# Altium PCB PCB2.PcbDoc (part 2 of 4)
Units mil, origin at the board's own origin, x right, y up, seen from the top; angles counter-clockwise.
Board outline 7170.03 x 5785.03 mil, 4 copper layers (Top Layer, GND, PWR, Bottom Layer), stack 22.378 mil thick; 348 components, 320 nets, 1937 pads, 429 vias.
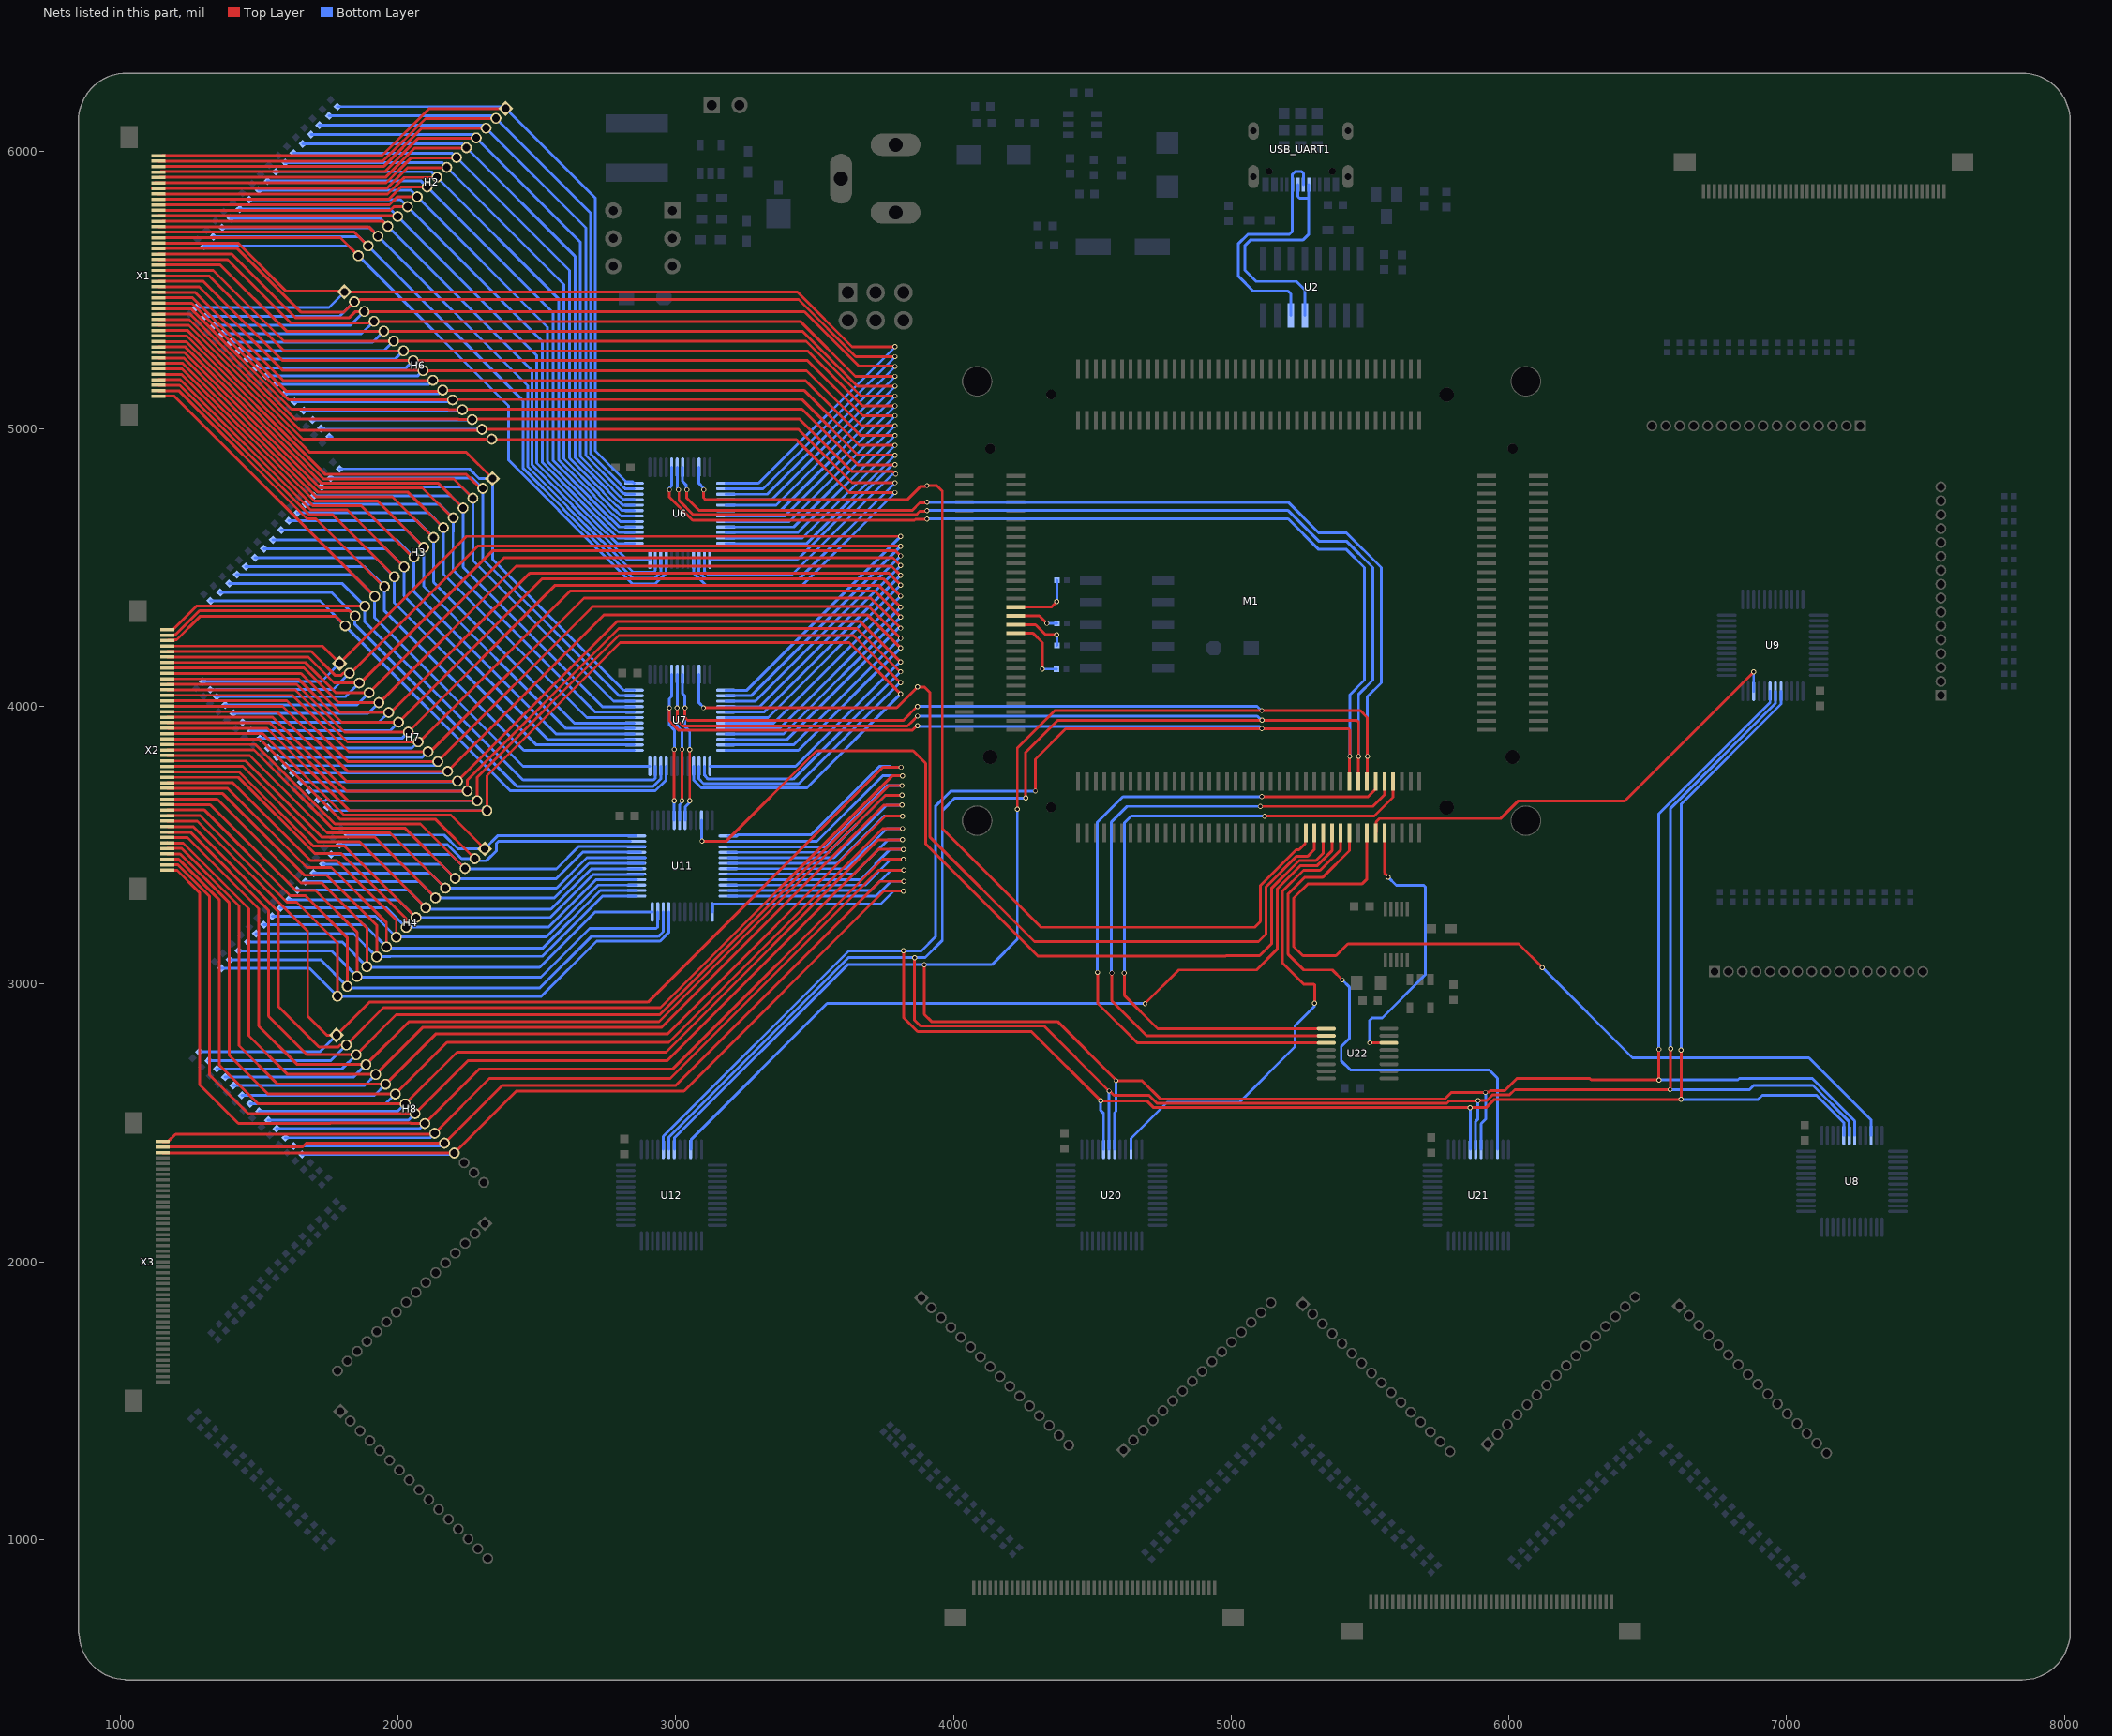
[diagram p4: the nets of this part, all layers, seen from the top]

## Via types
v1: diameter 18, hole 12, Top Layer to Bottom Layer, 429 vias

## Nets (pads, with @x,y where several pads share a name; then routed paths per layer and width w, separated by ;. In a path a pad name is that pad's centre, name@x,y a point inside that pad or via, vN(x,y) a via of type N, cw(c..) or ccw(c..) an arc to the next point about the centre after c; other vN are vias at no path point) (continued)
A2: M1.J4_63 U6.17 U7.17 U8.17 U9.17 U11.17 U12.17 U20.17 U21.17 | length 15635
  Top Layer w10: v1(2977.16,3994.49) 2977.16,3947.84 3011.53,3913.47 3851.3,3913.47 3867.84,3930 v1(3870,3930) ; v1(2977.16,4780) 2977.16,4753.53 3060.69,4670 3858.95,4670 3862.95,4674 3904,4674 v1(3905,4675) ; v1(2994.37,3660) v1(2994.37,3845) ; v1(3820,3119.81) 3820,2880 3870.63,2829.37 4280.63,2829.37 v1(4530,2580) 4695.68,2580 4720.68,2555 v1(5860,2555) 5917.53,2555 5947.53,2585 v1(6620,2585) v1(6620,2762.16) ; v1(4295,3695) 4295,3810 4405,3920 v1(5110,3920) 5421.15,3920 5427.01,3914.14 v1(5427.01,3820) 5426.24,3819.23 5426.24,3730.06 M1.J4_63@5425.47,3729.29 M1.J4_63@5425,3728.82
  Bottom Layer w10: U12.17@2955.47,2405.36 2955.47,2451.67 3623.61,3119.81 v1(3820,3119.81) 3884.81,3119.81 3935,3170 3935,3640 3990,3695 v1(4295,3695) ; v1(2977.16,4780) 2977.16,4785.94 2985.47,4794.25 U6.17@2985.47,4860.36 ; U7.17@2985.47,4115.36 2985.47,4035.47 2977.16,4027.16 v1(2977.16,3994.49) 2977.16,3932.84 2995,3915 2995,3845.63 v1(2994.37,3845) ; U11.17@2994.37,3590.71 v1(2994.37,3660) ; v1(3870,3930) 3871.53,3928.47 5099.37,3928.47 5107.84,3920 v1(5110,3920) ; v1(3905,4675) 5205,4675 5315,4565 5415,4565 5480,4500 5480,4095 5427.01,4042.01 v1(5427.01,3820) ; v1(4530,2580) 4530,2545.06 4540.47,2534.59 U20.17@4540.47,2405.36 ; v1(5860,2555) 5860.47,2554.53 U21.17@5860.47,2405.36 ; v1(6620,2585) 6897.15,2585 6912.15,2600 7107.14,2600 7205.47,2501.67 U8.17@7205.47,2455.36 ; v1(6620,2762.16) 6620,3648.8 6979.53,4008.33 U9.17@6979.53,4054.64
A3: M1.J4_65 U6.18 U7.18 U8.18 U9.18 U11.18 U12.18 U20.18 U21.18 | length 15711.1
  Top Layer w10: v1(3005.16,3995) 3005.16,3949.84 3025.53,3929.47 3834.47,3929.47 3852.52,3947.52 v1(3870,3965) ; v1(3010,4780) 3011.53,4778.47 3011.53,4741.78 3063.31,4690 3866.21,4690 3878.53,4702.32 3902.32,4702.32 v1(3905,4705) ; v1(3022.37,3660) v1(3022.37,3845) ; v1(3860,3095) 3860,2870 3880.94,2849.06 4325.94,2849.06 v1(4560,2615) 4562.16,2615 4577.84,2599.33 4704.2,2599.33 4732.52,2571 5776.27,2571 5785.27,2580 5888.26,2580 v1(5889.13,2580.87) ; v1(4260,3670) 4260,3835 4375,3950 5109.8,3950 v1(5110.31,3950.5) ; v1@5110,3950 5452.65,3950 5458.51,3944.14 v1(5458.51,3820) 5457.74,3819.23 5457.74,3730.06 M1.J4_65@5456.97,3729.29 ; v1@5890,2580 5890.87,2580.87 5920.77,2580.87 5940.9,2601 6001.94,2601 6020.94,2620 v1(6580,2620) 6581.53,2621.53 6581.53,2627.19 6582,2627.66 v1(6582,2767)
  Bottom Layer w10: U12.18@2975.16,2405.36 2975.36,2405.55 2975.36,2448.93 3622.23,3095.81 3859.19,3095.81 v1(3860,3095) 3860.81,3095.81 3898.24,3095.81 3960,3157.57 3960,3625 4005,3670 v1(4260,3670) ; U7.18@3005.16,4115.36 v1(3005.16,3995) 3005.16,3928.92 3023,3911.08 3023,3845.63 v1(3022.37,3845) ; U6.18@3005.16,4860.36 3005.16,4787 3010,4782.16 v1(3010,4780) ; U11.18@3014.06,3590.71 3014.06,3645.75 3022.37,3654.06 v1(3022.37,3660) ; v1(3870,3965) 5093.65,3965 5108.14,3950.5 v1(5110.31,3950.5) ; v1(3905,4705) 5205,4705 5315,4595 5415,4595 5510,4500 5510,4095 5458.51,4043.51 v1(5458.51,3820) ; v1(4560,2615) 4560.08,2614.92 4560.08,2405.44 U20.18@4560.16,2405.36 ; U21.18@5880.16,2405.36 5880.16,2505.75 5888.47,2514.06 5888.47,2580.21 v1(5889.13,2580.87) ; v1(6580,2620) 6865.97,2620 6880.97,2635 7094.77,2635 7225.16,2504.61 U8.18@7225.16,2455.36 ; v1(6582,2767) 6582,3633.42 6959.84,4011.26 U9.18@6959.84,4054.64
A4: M1.J4_67 U6.19 U7.19 U8.19 U9.19 U11.19 U12.19 U20.19 U21.19 | length 15781.3
  Top Layer w10: v1(3033.16,3995) 3033.16,3959.29 3042.45,3950 3820,3950 v1(3870,4000) ; v1(3040,4780) 3040,4749.75 3064.75,4725 3083.75,4706 3852.21,4706 3878.53,4732.32 3902.32,4732.32 v1(3905,4735) ; v1(3050.37,3660) v1(3050.37,3844.63) ; v1(3895,3070) 3895,2890.86 3920.8,2865.06 4374.94,2865.06 4581,2659 4581,2656.16 v1(4585,2652.16) 4679.19,2652.16 4744.36,2587 5769.65,2587 5791.65,2609 5850.98,2609 5851.98,2610 v1(5915,2610) 5916.53,2611.53 5928.8,2611.53 5934.27,2617 5985.74,2617 6028.74,2660 6290.79,2660 6295.79,2655 v1(6540,2655) v1(6540,2765) ; v1(4230,3630) 4230,3850 4365,3985 v1(5110,3985) 5465,3985 5490,3960 v1(5490,3820) 5489.23,3819.23 5489.23,3730.06 M1.J4_67@5488.46,3729.29
  Bottom Layer w10: U12.19@2994.84,2405.36 2994.84,2445.79 3619.05,3070 v1(3895,3070) 4138.43,3070 4230,3161.57 v1(4230,3630) ; U7.19@3024.84,4115.36 3024.84,4045.16 3033.16,4036.84 v1(3033.16,3995) 3033.16,3926.84 3050.37,3909.63 v1(3050.37,3844.63) ; U6.19@3024.84,4860.36 3024.84,4809.92 3038.47,4796.29 3038.47,4781.53 v1(3040,4780) ; U11.19@3033.74,3590.71 3033.74,3637.43 3050.37,3654.06 v1(3050.37,3660) ; v1(3870,4000) 5092.84,4000 5107.84,3985 v1(5110,3985) ; v1(3905,4735) 5205,4735 5315,4625 5415,4625 5540,4500 5540,4085 5490,4035 v1(5490,3820) ; U20.19@4579.84,2405.36 4579.84,2536.9 4585,2542.06 v1(4585,2652.16) ; U21.19@5899.84,2405.36 5899.84,2497.43 5916.47,2514.06 5916.47,2608.53 v1(5915,2610) ; v1(6540,2655) 6824.78,2655 6829.78,2660 7092.4,2660 7244.84,2507.56 U8.19@7244.84,2455.36 ; v1(6540,2765) 6540,3614.05 6940.16,4014.21 U9.19@6940.16,4054.64
A5: M1.J4_69 U22.11 | length 2612.8
  Top Layer w10: v1(4518.03,3041.97) 4519.56,3040.44 4519.56,2930.44 4661.61,2788.39 U22.11@5342.18,2788.39 ; v1(5110,3675) 5492.24,3675 5519.96,3702.72 M1.J4_69@5519.96,3729.29
  Bottom Layer w10: v1(4518.03,3041.97) 4518.03,3583.03 4610,3675 v1(5110,3675)
A6: M1.J4_71 U22.10 | length 2539.4
  Top Layer w10: v1(4570,3040) 4570,2940 4696.02,2813.98 U22.10@5342.18,2813.98 ; v1(5105,3640) 5510,3640 5551.46,3681.46 M1.J4_71@5551.46,3729.29
  Bottom Layer w10: v1(4570,3040) 4569.03,3040.97 4569.03,3584.03 4625,3640 v1(5105,3640)
A7: M1.J4_73 U22.9 | length 2459.8
  Top Layer w10: v1(4615,3040) 4615,2960 4735.43,2839.57 U22.9@5342.18,2839.57 ; v1(5120,3605) 5515,3605 5582.95,3672.95 M1.J4_73@5582.95,3729.29
  Bottom Layer w10: v1(4615,3040) 4615,3580 4640,3605 v1(5120,3605)
CH340_N: U2.6 USB_UART1.5 USB_UART1.7 | length 915.4
  Bottom Layer w10: U2.6@5215,5407.64 5215,5485 5205,5495 5080,5495 5025,5550 5025,5665 5060,5700 5210,5700 5220.47,5710.47 USB_UART1.5@5220.47,5878.05 5220.47,5915.47 5230,5925 5253.98,5925 5259.84,5919.14 USB_UART1.7@5259.84,5878.05
CH340_P: U2.5 USB_UART1.6 USB_UART1.8 | length 934.2
  Bottom Layer w10: USB_UART1.6@5240.16,5878.05 5240.16,5835.86 5246.02,5830 5279.53,5830 ; U2.5@5265,5407.64 5265,5500 5235,5530 5090,5530 5050,5570 5050,5660 5070,5680 5259.05,5680 5279.53,5700.47 5279.53,5830 ; USB_UART1.8@5279.53,5878.05 5279.53,5830
EN0: M1.J4_72 U22.6 | length 1048.1
  Top Layer w10: v1(5498.74,2788.39) U22.6@5567.82,2788.39 ; M1.J4_72@5551.46,3544.25 5551.46,3400.7 5565,3387.16 v1(5565,3385)
  Bottom Layer w10: v1(5498.74,2788.39) 5498.74,2869.66 5507.47,2878.39 5543.39,2878.39 5699,3034 5699,3350.14 5693.14,3356 5594,3356 v1(5565,3385)
EN1: M1.J4_54 U6.22 | length 3915.6
  Top Layer w10: v1(3100.53,4780) 3100.53,4750.86 3106.39,4745 3835,4745 3882.32,4792.32 3902.32,4792.32 v1(3905,4795) 3940,4795 3960,4775 3960,3560 4315.43,3204.57 5084.57,3204.57 5105,3225 5105,3355 5233.78,3483.78 5243.78,3483.78 5266.06,3506.06 5266.06,3542.36 M1.J4_54@5267.95,3544.25
  Bottom Layer w10: U6.22@3083.9,4860.36 3083.9,4802.57 3100.53,4785.94 v1(3100.53,4780)
EN2: M1.J4_56 U7.22 | length 3339
  Top Layer w10: v1(3100,3995) 3796.06,3995 3870,4068.94 v1(3870,4070) 3895,4070 3916,4049 3916,3529 4291.61,3153.39 5098.39,3153.39 5125,3180 5125,3350 5236,3461 5276,3461 5299.45,3484.45 M1.J4_56@5299.45,3544.25
  Bottom Layer w10: U7.22@3083.9,4115.36 3083.9,4012.84 3100,3996.74 v1(3100,3995)
EN3: M1.J4_58 U11.22 | length 3266.9
  Top Layer w10: v1(3095,3515) 3181.98,3515 3506.98,3840 3855,3840 3900,3795 3900,3505 4304,3101 4980.85,3101 4982.05,3102.2 5102.2,3102.2 5145,3145 5145,3345 5245,3445 5305,3445 5330.95,3470.95 M1.J4_58@5330.95,3544.25
  Bottom Layer w10: U11.22@3092.8,3590.71 3092.8,3519.36 3095,3517.16 v1(3095,3515)
EN4: M1.J4_60 U12.22 | length 2965
  Top Layer w10: v1(4690,2930) 4811.02,3051.02 5091.02,3051.02 5165,3125 5165,3342.37 5248.63,3426 5308.63,3426 5362.44,3479.81 M1.J4_60@5362.44,3544.25
  Bottom Layer w10: U12.22@3053.9,2405.36 3053.9,2435.55 3057.07,2438.72 3057.07,2442.12 3544.95,2930 v1(4690,2930)
EN5: M1.J4_62 U20.22 | length 1756.4
  Top Layer w10: v1(5300,2931) 5300,2997.84 5298,2999.84 5288.03,2999.84 5260.9,2999.84 5185,3075.74 5185,3335 5260,3410 5320,3410 5393.98,3483.98 M1.J4_62@5393.98,3544.25
  Bottom Layer w10: U20.22@4638.9,2405.36 4639.1,2405.55 4639.1,2444.6 4769.05,2574.55 5029.55,2574.55 5230,2775 5230,2850 5298.53,2918.53 5298.53,2929.53 v1(5300,2931)
EN6: M1.J4_64 U21.22 | length 1957.9
  Top Layer w10: v1(5400,3015) 5363.98,3051.02 5260.9,3051.02 5205,3106.92 5205,3325 5265,3385 5330,3385 5425.47,3480.47 M1.J4_64@5425.47,3544.25
  Bottom Layer w10: v1(5400,3015) 5425,2990 5425,2804 5396,2775 5396,2724 5428.67,2691.33 5928.67,2691.33 5958.9,2661.1 U21.22@5958.9,2405.36
EN7: M1.J4_68 U8.22 | length 3061.1
  Top Layer w10: M1.J4_68@5488.46,3544.25 5488.46,3378.46 5470,3360 5275,3360 5225,3310 5225,3135 5257.8,3102.2 5377.2,3102.2 5420,3145 6035,3145 v1(6120,3060)
  Bottom Layer w10: v1(6120,3060) 6445,2735 7080,2735 7303.9,2511.1 U8.22@7303.9,2455.36
EN8: M1.J4_70 U9.22 | length 1692.8
  Top Layer w10: M1.J4_70@5519.96,3544.25 5521.71,3546 5521.71,3584.07 5533.82,3596.18 5969.61,3596.18 6032.17,3658.74 6415.94,3658.74 v1(6881.1,4123.9)
  Bottom Layer w10: U9.22@6881.1,4054.64 v1(6881.1,4123.9)
FPGA_TCK: M1.J3_37 R1.1 | length 255.5
  Top Layer w10: M1.J3_37@4224.54,4262.84 4287.16,4262.84 4320,4230 v1(4320,4135)
  Bottom Layer w10: v1(4320,4135) 4320.5,4134.5 4370.5,4134.5 R1.1@4371,4134
FPGA_TDI: M1.J3_31 R4.1 | length 232.6
  Top Layer w10: M1.J3_31@4224.54,4357.32 4352.32,4357.32 v1(4372,4377)
  Bottom Layer w10: v1(4372,4377) R4.1@4372,4454
FPGA_TDO: M1.J3_35 R2.1 | length 201.5
  Top Layer w10: M1.J3_35@4224.54,4294.33 4295.67,4294.33 4332,4258 v1(4372,4258)
  Bottom Layer w10: R2.1@4372,4219 v1(4372,4258)
FPGA_TMS: M1.J3_33 R3.1 | length 158.6
  Top Layer w10: M1.J3_33@4224.54,4325.83 4309.17,4325.83 v1(4336,4299)
  Bottom Layer w10: v1(4336,4299) R3.1@4372,4299
G0: H2.1 R14.2 U6.12 X1.1 | length 3469.6
  Top Layer w10: X1.1@1151.42,5983.07 1942.75,5983.07 2111.85,6152.17 2366.4,6152.17 2367.07,6152.84 H2.1@2387.84,6152.84
  Bottom Layer w10: R14.2@1781.96,6159.43 2381.26,6159.43 H2.1@2387.84,6152.84 2710,5830.69 2710,4920 2821.73,4808.27 2844.64,4808.27 U6.12@2849.64,4803.27
G1: H2.2 R16.2 U6.11 X1.2 | length 3442.2
  Top Layer w10: X1.2@1137.7,5963.39 1945.69,5963.39 2099.12,6116.82 2351.82,6116.82 H2.2@2352.49,6117.49
  Bottom Layer w10: R16.2@1751.96,6125.94 2344.04,6125.94 H2.2@2352.49,6117.49 2694,5775.97 2694,4908.15 2803.21,4798.94 2803.21,4796.43 2812.88,4786.76 2816.27,4786.76 2819.45,4783.58 U6.11@2849.64,4783.58
G2: H2.3 R18.2 U6.10 X1.3 | length 3389.2
  Top Layer w10: X1.3@1149.42,5945 1949.93,5945 2086.39,6081.46 2316.46,6081.46 H2.3@2317.13,6082.13
  Bottom Layer w10: R18.2@1716.96,6092.44 2306.82,6092.44 H2.3@2317.13,6082.13 2676.4,5722.87 2676.4,4902.76 2787.21,4791.95 2787.21,4789.8 2806.26,4770.76 2808.4,4770.76 2812.09,4767.07 2816.28,4767.07 2819.45,4763.9 U6.10@2849.64,4763.9
G3: H2.4 R20.2 U6.9 X1.4 | length 3347.4
  Top Layer w10: X1.4@1145.59,5925 1952.56,5925 2073.66,6046.11 2281.11,6046.11 H2.4@2281.78,6046.78
  Bottom Layer w10: R20.2@1686.96,6058.95 2269.61,6058.95 H2.4@2281.78,6046.78 2656.71,5671.84 2656.71,4899.82 2771.21,4785.32 2771.21,4783.18 2799.63,4754.76 2801.77,4754.76 2812.12,4744.41 2849.45,4744.41 U6.9@2849.64,4744.21
G4: H2.5 R22.2 U6.8 X1.5 | length 3304.5
  Top Layer w10: X1.5@1142.83,5905 1955.18,5905 2060.93,6010.75 2245.75,6010.75 H2.5@2246.42,6011.42
  Bottom Layer w10: R22.2@1656.96,6025.45 2232.39,6025.45 H2.5@2246.42,6011.42 2637.03,5620.82 2637.03,4896.87 2755.21,4778.69 2755.21,4776.55 2793,4738.76 2795.14,4738.76 2809.18,4724.73 2849.45,4724.73 U6.8@2849.64,4724.53
G5: H2.6 R24.2 U6.7 X1.6 | length 3280.2
  Top Layer w10: X1.6@1124.56,5885 1957.81,5885 2048.21,5975.4 2210.4,5975.4 H2.6@2211.07,5976.07
  Bottom Layer w10: R24.2@1624.01,5991.96 2195.17,5991.96 H2.6@2211.07,5976.07 2617.34,5569.8 2617.34,4893.94 2739.21,4772.06 2739.21,4769.92 2786.37,4722.76 2788.52,4722.76 2806.24,4705.04 2849.45,4705.04 U6.7@2849.64,4704.84
G6: H2.7 R26.2 U6.6 X1.7 | length 3244.1
  Top Layer w10: X1.7@1115.01,5865 1960.44,5865 2035.48,5940.04 2175.04,5940.04 H2.7@2175.71,5940.71
  Bottom Layer w10: R26.2@1594.01,5958.46 2157.96,5958.46 H2.7@2175.71,5940.71 2597.66,5518.76 2597.66,4890.99 2723.21,4765.44 2723.21,4763.29 2779.75,4706.76 2781.89,4706.76 2803.49,4685.16 U6.6@2849.64,4685.16
G7: H2.8 R28.2 U6.5 X1.8 | length 3182.1
  Top Layer w10: X1.8@1135.49,5845 1963.07,5845 2022.75,5904.68 2139.68,5904.68 H2.8@2140.36,5905.36
  Bottom Layer w10: R28.2@1559.91,5924.97 2120.74,5924.97 H2.8@2140.36,5905.36 2577.97,5467.74 2577.97,4888.05 2707.21,4758.81 2707.21,4756.67 2773.12,4690.76 2775.26,4690.76 2800.55,4665.47 U6.5@2849.64,4665.47
G8: H2.9 R30.2 U6.4 X1.9 | length 3138.7
  Top Layer w10: X1.9@1133.06,5825.6 1966.29,5825.6 2010.02,5869.33 2104.33,5869.33 H2.9@2105,5870
  Bottom Layer w10: R30.2@1529.91,5891.47 2083.53,5891.47 H2.9@2105,5870 2558.29,5416.71 2558.29,4885.1 2691.21,4752.18 2691.21,4750.04 2766.49,4674.76 2768.63,4674.76 2797.6,4645.79 U6.4@2849.64,4645.79
G9: H2.10 R32.2 U6.3 X1.10 | length 3089.2
  Top Layer w10: X1.10@1137.76,5805.91 1969.23,5805.91 1997.3,5833.97 2068.97,5833.97 H2.10@2069.64,5834.64
  Bottom Layer w10: R32.2@1499.01,5857.98 2046.31,5857.98 H2.10@2069.64,5834.64 2538.6,5365.69 2538.6,4882.17 2675.21,4745.55 2675.21,4743.41 2759.86,4658.76 2762.01,4658.76 2794.66,4626.1 U6.3@2849.64,4626.1
G10: H2.11 R34.2 U6.2 X1.11 | length 3051.9
  Top Layer w10: X1.11@1134.66,5785.32 1971.26,5785.32 1984.57,5798.62 2033.62,5798.62 H2.11@2034.29,5799.29
  Bottom Layer w10: R34.2@1464.01,5824.49 2009.09,5824.49 H2.11@2034.29,5799.29 2518.92,5314.66 2518.92,4879.22 2659.21,4738.93 2659.21,4736.78 2753.24,4642.76 2755.38,4642.76 2791.72,4606.42 U6.2@2849.64,4606.42
G11: H2.12 R36.2 U6.1 X1.12 | length 3008.8
  Top Layer w10: X1.12@1137.76,5766.54 1996.33,5766.54 H2.12@1998.93,5763.93
  Bottom Layer w10: R36.2@1430.09,5790.99 1971.88,5790.99 H2.12@1998.93,5763.93 2499.23,5263.64 2499.23,4876.28 2643.21,4732.3 2643.21,4730.16 2746.61,4626.76 2748.75,4626.76 2788.78,4586.73 U6.1@2849.64,4586.73
G12: H2.13 R38.2 U6.48 X1.13 | length 3040.1
  Top Layer w10: X1.13@1151.42,5746.85 1945.31,5746.85 H2.13@1963.58,5728.58
  Bottom Layer w10: R38.2@1397.14,5757.5 1934.66,5757.5 H2.13@1963.58,5728.58 2483.23,5208.93 2483.23,4869.66 2627.21,4725.67 2627.21,4723.53 2739.98,4610.76 2742.12,4610.76 2824.96,4527.92 2906.26,4527.92 2906.73,4528.4 U6.48@2906.73,4529.64
G13: H2.14 R40.2 U6.47 X1.14 | length 3092.6
  Top Layer w10: X1.14@1137.76,5727.17 1894.28,5727.17 H2.14@1928.22,5693.22
  Bottom Layer w10: R40.2@1367.14,5724 1897.44,5724 H2.14@1928.22,5693.22 2467.23,5154.22 2467.23,4863.03 2611.21,4719.04 2611.21,4716.9 2733.35,4594.76 2735.5,4594.76 2847.04,4483.21 2920.56,4483.21 2926.42,4489.07 U6.47@2926.42,4529.64
G14: H2.15 R42.2 U6.46 X1.15 | length 3097
  Top Layer w10: X1.15@1136.07,5708.39 1842.35,5708.39 H2.15@1892.87,5657.87
  Bottom Layer w10: R42.2@1335.09,5690.51 1860.23,5690.51 H2.15@1892.87,5657.87 2451.23,5099.51 2451.23,4856.4 2595.21,4712.42 2595.21,4710.27 2726.73,4578.76 2728.87,4578.76 2846.27,4461.35 2924.13,4461.35 2946.1,4483.33 U6.46@2946.1,4529.64
G15: H2.16 R44.2 U6.45 X1.16 | length 3092.9
  Top Layer w10: X1.16@1137.76,5687.8 1792.23,5687.8 H2.16@1857.51,5622.51
  Bottom Layer w10: R44.2@1302.14,5657.01 1823.01,5657.01 H2.16@1857.51,5622.51 2398.24,5081.79 2398.24,4886.76 2579.21,4705.79 ; 2579.21,4703.65 2720.1,4562.76 2722.24,4562.76 2843.79,4441.21 2926.61,4441.21 2965.79,4480.39 U6.45@2965.79,4529.64
G16: H6.1 R46.2 U6.25 X1.17 | length 4182.8
  Top Layer w10: X1.17@1137.76,5668.11 1424.52,5668.11 1597.63,5495 1784.23,5495 1786.74,5492.49 1789.26,5495 1807.51,5495 H6.1@1810.03,5492.49 ; H6.1@1807.51,5492.49 1828.28,5492.49 1828.95,5491.82 3438.18,5491.82 3635.04,5294.96 v1(3790,5294.96)
  Bottom Layer w10: R46.2@1272.59,5436.51 1751.54,5436.51 H6.1@1807.51,5492.49 ; U6.25@3180.36,4803.27 3298.31,4803.27 v1(3790,5294.96)
G17: H6.2 R48.2 U6.26 X1.18 | length 4209.9
  Top Layer w10: X1.18@1137.76,5648.43 1421.57,5648.43 1650,5420 1805.74,5420 H6.2@1837.3,5451.56 ; H6.2@1842.87,5457.13 1848.49,5462.75 1861.16,5462.75 1863.41,5465 3442.37,5465 3647.91,5259.46 v1(3790,5259.46)
  Bottom Layer w10: R48.2@1304.64,5403.56 1789.3,5403.56 H6.2@1842.87,5457.13 ; U6.26@3180.36,4783.58 3314.12,4783.58 v1(3790,5259.46)
G18: H6.3 R50.2 U6.27 X1.19 | length 4192.7
  Top Layer w10: X1.19@1137.76,5628.74 1401.26,5628.74 1630,5400 1825,5400 1846.78,5421.78 H6.3@1878.22,5421.78 ; H6.3@1889.05,5410.95 1899.21,5421.11 3463.64,5421.11 3659.25,5225.5 3788.47,5225.5 v1(3790,5223.97)
  Bottom Layer w10: R50.2@1337.59,5371.51 1827.96,5371.51 H6.3@1878.22,5421.78 ; U6.27@3180.36,4763.9 3329.93,4763.9 v1(3790,5223.97)
G19: H6.4 R52.2 U6.28 X1.20 | length 4190
  Top Layer w10: X1.20@1137.76,5609.06 1385.94,5609.06 1615,5380 1907.16,5380 H6.4@1913.58,5386.42 3448.58,5386.42 3646.53,5188.47 v1(3790,5188.47)
  Bottom Layer w10: R52.2@1367.59,5341.51 1868.67,5341.51 H6.4@1913.58,5386.42 ; U6.28@3180.36,4744.21 3345.74,4744.21 v1(3790,5188.47)
G20: H6.5 R54.2 U6.29 X1.21 | length 4187.8
  Top Layer w10: X1.21@1137.76,5589.37 1360.63,5589.37 1598.93,5351.07 H6.5@1948.93,5351.07 3456.56,5351.07 3654.65,5152.97 v1(3790,5152.97)
  Bottom Layer w10: R54.2@1397.59,5311.51 1909.38,5311.51 H6.5@1948.93,5351.07 ; U6.29@3180.36,4724.53 3361.56,4724.53 v1(3790,5152.97)
G21: H6.6 R56.2 U6.30 X1.22 | length 4191
  Top Layer w10: X1.22@1137.76,5569.69 1335.31,5569.69 1590,5315 1984.29,5315 1984.33,5315.04 3469.96,5315.04 3667.52,5117.48 v1(3790,5117.48)
  Bottom Layer w10: R56.2@1427.59,5281.51 1950.09,5281.51 H6.6@1984.29,5315.71 ; U6.30@3180.36,4704.84 3377.36,4704.84 v1(3790,5117.48)
G22: H6.7 R58.2 U6.31 X1.23 | length 4194.1
  Top Layer w10: X1.23@1137.76,5550 1320,5550 1590,5280 3475,5280 3673.02,5081.98 v1(3790,5081.98)
  Bottom Layer w10: R58.2@1457.59,5251.51 1990.8,5251.51 H6.7@2019.64,5280.36 ; U6.31@3180.36,4685.16 3393.18,4685.16 v1(3790,5081.98)
G23: H6.8 R60.2 U6.32 X1.24 | length 4195.2
  Top Layer w10: X1.24@1137.76,5530.32 1299.68,5530.32 1585,5245 H6.8@2055,5245 3475,5245 3673.51,5046.49 v1(3790,5046.49)
  Bottom Layer w10: R60.2@1490.54,5219.47 2029.46,5219.47 H6.8@2055,5245 ; U6.32@3180.36,4665.47 3408.98,4665.47 v1(3790,5046.49)
G24: H6.9 R62.2 U6.33 X1.25 | length 4186.4
  Top Layer w10: X1.25@1137.76,5510.63 1284.37,5510.63 1585.36,5209.64 H6.9@2090.36,5209.64 ; H6.9@2101.19,5198.81 2111.34,5208.97 3471.03,5208.97 3669.01,5010.99 v1(3790,5010.99)
  Bottom Layer w10: R62.2@1525.54,5189.47 2070.18,5189.47 H6.9@2090.36,5209.64 ; U6.33@3180.36,4645.79 3424.8,4645.79 v1(3790,5010.99)
G25: H6.10 R64.2 U6.34 X1.26 | length 4191.4
  Top Layer w10: X1.26@1137.76,5490.95 1269.05,5490.95 1586.38,5173.62 3466.38,5173.62 3664.5,4975.5 v1(3790,4975.5)
  Bottom Layer w10: R64.2@1560.54,5159.47 2110.89,5159.47 H6.10@2125.71,5174.29 ; U6.34@3180.36,4626.1 3440.6,4626.1 v1(3790,4975.5)
G26: H6.11 R66.2 U6.35 X1.27 | length 4196.4
  Top Layer w10: X1.27@1137.76,5471.26 1261.03,5471.26 1597.29,5135 2161.07,5135 2164.33,5138.26 3461.74,5138.26 3660,4940 v1(3790,4940)
  Bottom Layer w10: R66.2@1592.59,5126.51 2148.65,5126.51 H6.11@2161.07,5138.93 ; U6.35@3180.36,4606.42 3456.42,4606.42 v1(3790,4940)
G27: H6.12 R68.2 U6.36 X1.28 | length 4193.2
  Top Layer w10: X1.28@1137.76,5451.58 1258.08,5451.58 1606.09,5103.58 H6.12@2196.42,5103.58 ; H6.12@2195.87,5104.25 2196.42,5104.8 3455.2,5104.8 3655.5,4904.5 v1(3790,4904.5)
  Bottom Layer w10: R68.2@1627.59,5096.51 2189.36,5096.51 H6.12@2196.42,5103.58 ; U6.36@3180.36,4586.73 3472.23,4586.73 v1(3790,4904.5)
G28: H6.13 R70.2 U6.37 X1.29 | length 4266.4
  Top Layer w10: X1.29@1137.76,5431.89 1255.15,5431.89 1617.04,5070 2180.95,5070 2182.05,5068.89 2230.67,5068.89 2231.78,5070 3455,5070 3655,4870 v1(3790,4870)
  Bottom Layer w10: R70.2@1660.54,5064.47 2228.02,5064.47 H6.13@2231.78,5068.22 ; U6.37@3123.27,4529.64 3123.39,4529.64 3123.74,4530 3440,4530 3778.47,4868.47 3788.47,4868.47 v1(3790,4870)
G29: H6.14 R72.2 U6.38 X1.30 | length 4353.5
  Top Layer w10: X1.30@1137.76,5412.21 1252.2,5412.21 1630.41,5034 2216.95,5034 2217.41,5033.54 2266.67,5033.54 2267.13,5034 3446,5034 3634,4846 3780.78,4846 3789.81,4836.97 v1(3791.97,4836.97)
  Bottom Layer w10: R72.2@1692.59,5031.51 2265.78,5031.51 H6.14@2267.13,5032.87 ; U6.38@3103.58,4529.64 3103.58,4486.27 3113.85,4476 3421,4476 3780.44,4835.44 3790.44,4835.44 v1(3791.97,4836.97)
G30: H6.15 R74.2 U6.39 X1.31 | length 4384
  Top Layer w10: X1.31@1137.76,5392.52 1249.26,5392.52 1646.78,4995 2302.49,4995 2304.33,4996.84 3443.16,4996.84 3635,4805 v1(3790,4805)
  Bottom Layer w10: R74.2@1722.59,5001.51 1729.67,5001.51 1733.67,4997.51 1748,4997.51 1748.39,4997.9 2302.1,4997.9 H6.15@2302.49,4997.51 ; U6.39@3083.9,4529.64 3083.9,4483.33 3107.23,4460 3445,4460 v1(3790,4805)
G31: H6.16 R76.2 U6.40 X1.32 | length 4422.5
  Top Layer w10: X1.32@1137.76,5372.84 1138.66,5371.94 1247.22,5371.94 1657,4962.16 2335.69,4962.16 2337.84,4960 3435,4960 3625,4770 v1(3790,4770)
  Bottom Layer w10: R76.2@1752.59,4971.51 1759.67,4971.51 1769.02,4962.16 H6.16@2337.84,4962.16 ; U6.40@3064.21,4529.64 3064.21,4480.39 3108.2,4436.4 3456.4,4436.4 v1(3790,4770)
G32: H3.1 R78.2 U7.12 X1.33 | length 2983.2
  Top Layer w10: X1.33@1137.76,5353.15 1243.38,5353.15 1681.53,4915 2245.71,4915 H3.1@2340.36,4820.36
  Bottom Layer w10: R78.2@1790,4855 2257.63,4855 2292.27,4820.36 H3.1@2340.36,4820.36 2340.36,4529.64 2811.53,4058.47 2849.45,4058.47 U7.12@2849.64,4058.27
G33: H3.2 R80.2 U7.11 X1.34 | length 2971.3
  Top Layer w10: X1.34@1137.76,5333.47 1240.43,5333.47 1738.9,4835 2246.67,4835 H3.2@2310.57,4771.1
  Bottom Layer w10: R80.2@1757.95,4822.05 2267.95,4822.05 H3.2@2305,4785 2305,4530 2796.42,4038.58 U7.11@2849.64,4038.58
G34: H3.3 R82.2 U7.10 X1.35 | length 2941
  Top Layer w10: X1.35@1137.76,5313.78 1237.49,5313.78 1732.27,4819 2200.29,4819 H3.3@2269.64,4749.64
  Bottom Layer w10: R82.2@1725,4790 2229.29,4790 H3.3@2269.64,4749.64 2269.65,4525.35 2776.1,4018.9 U7.10@2849.64,4018.9
G35: H3.4 R84.2 U7.9 X1.36 | length 2928.7
  Top Layer w10: X1.36@1137.76,5294.1 1234.55,5294.1 1725.65,4803 2145.58,4803 H3.4@2234.29,4714.29
  Bottom Layer w10: R84.2@1697.05,4757.95 2190.63,4757.95 2224.24,4724.34 H3.4@2234.29,4714.29 2234.29,4500.71 2735.79,3999.21 U7.9@2849.64,3999.21
G36: H3.5 R86.2 U7.8 X1.37 | length 2918
  Top Layer w10: X1.37@1137.76,5274.41 1231.61,5274.41 1719.02,4787 2088,4787 H3.5@2202.99,4672.01
  Bottom Layer w10: R86.2@1667.05,4727.95 2149.92,4727.95 H3.5@2198.93,4678.93 2198.93,4627.3 2198.23,4626.6 2198.23,4491.77 2710.47,3979.53 U7.8@2849.64,3979.53
G37: H3.6 R88.2 U7.7 X1.38 | length 2908.6
  Top Layer w10: X1.38@1137.76,5254.73 1228.66,5254.73 1712.39,4771 2036.16,4771 H3.6@2173.93,4633.23
  Bottom Layer w10: R88.2@1637.95,4697.05 2110.11,4697.05 H3.6@2163.58,4643.58 2163.58,4476.42 2680.16,3959.84 U7.7@2849.64,3959.84
G38: H3.7 R90.2 U7.6 X1.39 | length 2891.8
  Top Layer w10: X1.39@1137.76,5235.04 1225.72,5235.04 1705.76,4755 1980,4755 H3.7@2129.96,4605.04
  Bottom Layer w10: R90.2@1607.05,4667.95 2068.5,4667.95 2120.45,4616 H3.7@2128.22,4608.22 2128.22,4446.78 2634.84,3940.16 U7.6@2849.64,3940.16
G39: H3.8 R92.2 U7.5 X1.40 | length 2884.7
  Top Layer w10: X1.40@1137.76,5215.36 1222.78,5215.36 1699.14,4739 1926.74,4739 H3.8@2103.76,4561.98
  Bottom Layer w10: R92.2@1580,4635 2030.74,4635 H3.8@2092.87,4572.87 2092.87,4432.13 2604.53,3920.47 U7.5@2849.64,3920.47
G40: H3.9 R94.2 U7.4 X1.41 | length 2844.9
  Top Layer w10: X1.41@1137.76,5195.67 1219.84,5195.67 1692.51,4723 1867,4723 H3.9@2049.01,4540.99
  Bottom Layer w10: R94.2@1550,4600 1995.03,4600 H3.9@2057.51,4537.51 2057.51,4412.49 2569.21,3900.79 U7.4@2849.64,3900.79
G41: H3.10 R96.2 U7.3 X1.42 | length 2852
  Top Layer w10: X1.42@1137.76,5175.99 1216.89,5175.99 1685.88,4707 1817.32,4707 H3.10@2029.44,4494.88
  Bottom Layer w10: R96.2@1517.05,4567.95 1956.37,4567.95 2014.54,4509.78 H3.10@2022.16,4502.16 2022.16,4397.84 2538.9,3881.1 U7.3@2849.64,3881.1
G42: H3.11 R98.2 U7.2 X1.43 | length 2830
  Top Layer w10: X1.43@1137.76,5156.3 1213.95,5156.3 1679.25,4691 1764,4691 H3.11@1985,4470
  Bottom Layer w10: R98.2@1485,4535 1918.61,4535 H3.11@1986.8,4466.8 1986.8,4373.2 2498.58,3861.42 U7.2@2849.64,3861.42
G43: H3.12 R100.2 U7.1 X1.44 | length 2822.1
  Top Layer w10: X1.44@1137.76,5136.62 1211.01,5136.62 1672.63,4675 1705,4675 H3.12@1945.88,4434.12
  Bottom Layer w10: R100.2@1452.05,4502.95 1879.94,4502.95 H3.12@1951.45,4431.45 1951.45,4343.55 2453.27,3841.73 U7.1@2849.64,3841.73
G44: H3.13 R102.2 U7.48 X1.45 | length 2894.8
  Top Layer w10: X1.45@1137.76,5116.93 1195.25,5116.93 H3.13@1916.09,4396.09
  Bottom Layer w10: R102.2@1420,4475 1837.18,4475 H3.13@1916.09,4396.09 1916.09,4318.91 2450.36,3784.64 U7.48@2906.73,3784.64
G45: H3.14 R104.2 U7.47 X2.1 | length 2652.4
  Top Layer w10: X2.1@1170,4276.18 1189.68,4276.18 1274.24,4360.74 H3.14@1880.74,4360.74
  Bottom Layer w10: R104.2@1392.05,4442.95 1798.52,4442.95 H3.14@1880.74,4360.74 1880.74,4304.26 2450,3735 2920.15,3735 2926.42,3741.27 U7.47@2926.42,3784.64
G46: H3.15 R106.2 U7.46 X2.2 | length 2670.3
  Top Layer w10: X2.2@1169.94,4256.5 1170.85,4257.41 1194.52,4257.41 1196.39,4259.27 1200.15,4259.27 1285.61,4344.74 1824.84,4344.74 1844.19,4325.38 H3.15@1845.38,4325.38
  Bottom Layer w10: R106.2@1360,4410 1760.76,4410 H3.15@1845.38,4325.38 1845.38,4294.62 2427.79,3712.21 2919.98,3712.21 2946.1,3738.33 U7.46@2946.1,3784.64
G47: H3.16 R108.2 U7.45 X2.3 | length 2680.6
  Top Layer w10: X2.3@1170,4236.81 1170.91,4237.72 1194.57,4237.72 1196.45,4239.59 1203.09,4239.59 1288.5,4325 1775.05,4325 H3.16@1810.03,4290.03
  Bottom Layer w10: R108.2@1325,4380 1720.05,4380 H3.16@1810.03,4290.03 ; H3.16@1810.03,4290.03 2403.79,3696.21 2926.61,3696.21 2965.79,3735.39 U7.45@2965.79,3784.64
G48: H7.1 R110.2 U7.25 X2.4 | length 4233.2
  Top Layer w10: X2.4@1170,4217.13 1727.87,4217.13 H7.1@1789.84,4155.16 2246.64,4611.97 v1(3810,4611.97)
  Bottom Layer w10: R110.2@1297.58,4089.82 1724.49,4089.82 H7.1@1789.84,4155.16 ; U7.25@3180.36,4058.27 3256.3,4058.27 v1(3810,4611.97)
G49: H7.2 R112.2 U7.26 X2.5 | length 4240.7
  Top Layer w10: X2.5@1170,4197.44 1687.56,4197.44 1772.67,4112.33 1796.05,4112.33 1803.53,4119.81 H7.2@1825.19,4119.81 ; H7.2@1830.23,4120.23 2286.97,4576.97 v1(3810,4576.97)
  Bottom Layer w10: R112.2@1324.31,4060.21 1342.38,4060.21 1343.38,4061.21 1766.59,4061.21 H7.2@1825.19,4119.81 ; U7.26@3180.36,4038.58 3271.61,4038.58 v1(3810,4576.97)
G50: H7.3 R114.2 U7.27 X2.6 | length 4261.8
  Top Layer w10: X2.6@1170,4177.76 1677.24,4177.76 1770.55,4084.45 H7.3@1860.55,4084.45 ; H7.3@1862.5,4082.5 2340,4560 3791.97,4560 v1(3810,4541.97)
  Bottom Layer w10: R114.2@1347.58,4034.82 1810.91,4034.82 H7.3@1860.55,4084.45 ; U7.27@3180.36,4018.9 3286.93,4018.9 v1(3810,4541.97)
G51: H7.4 R116.2 U7.28 X2.7 | length 4274.6
  Top Layer w10: X2.7@1170,4158.07 1666.93,4158.07 1775.9,4049.1 H7.4@1895.9,4049.1 2381.8,4535 3781.97,4535 v1(3810,4506.97)
  Bottom Layer w10: R116.2@1377.58,4004.82 1851.63,4004.82 H7.4@1895.9,4049.1 ; U7.28@3180.36,3999.21 3302.24,3999.21 v1(3810,4506.97)
G52: H7.5 R118.2 U7.29 X2.8 | length 4278.4
  Top Layer w10: X2.8@1170,4138.39 1661.61,4138.39 1786.26,4013.74 H7.5@1931.26,4013.74 ; H7.5@1934.65,4014.65 2425,4505 3776.97,4505 v1(3810,4471.97)
  Bottom Layer w10: R118.2@1407.58,3974.82 1892.33,3974.82 H7.5@1931.26,4013.74 ; U7.29@3180.36,3979.53 3317.56,3979.53 v1(3810,4471.97)
G53: H7.6 R120.2 U7.30 X2.9 | length 4291.8
  Top Layer w10: X2.9@1170,4118.7 1651.3,4118.7 1791.61,3978.39 H7.6@1966.61,3978.39 ; H7.6@1970,3975 2475,4480 3766.97,4480 v1(3810,4436.97)
  Bottom Layer w10: R120.2@1440.53,3942.77 1931,3942.77 H7.6@1966.61,3978.39 ; U7.30@3180.36,3959.84 3332.87,3959.84 v1(3810,4436.97) v1@3808.03,4436.97
G54: H7.7 R122.2 U7.31 X2.10 | length 4298.8
  Top Layer w10: X2.10@1170,4099.02 1640.98,4099.02 1796.97,3943.03 H7.7@2001.97,3943.03 ; H7.7@2008.57,3948.57 2520,4460 3746.97,4460 v1(3810,4396.97)
  Bottom Layer w10: R122.2@1470.53,3912.77 1971.71,3912.77 H7.7@2001.97,3943.03 ; U7.31@3180.36,3940.16 3353.19,3940.16 v1(3810,4396.97)
G55: H7.8 R124.2 U7.32 X2.11 | length 4317.7
  Top Layer w10: X2.11@1170,4079.33 1635.67,4079.33 1807.32,3907.68 H7.8@2037.32,3907.68 2566.05,4436.4 3730.57,4436.4 v1(3810,4356.97)
  Bottom Layer w10: R124.2@1502.58,3884.82 2014.47,3884.82 H7.8@2037.32,3907.68 ; U7.32@3180.36,3920.47 3373.5,3920.47 v1(3810,4356.97)
G56: H7.9 R126.2 U7.33 X2.12 | length 4333.1
  Top Layer w10: X2.12@1170,4059.65 1630.35,4059.65 1817.68,3872.32 H7.9@2072.68,3872.32 ; H7.9@2075,3870 2620,4415 3716.97,4415 v1(3810,4321.97)
  Bottom Layer w10: R126.2@1532.58,3849.82 2050.18,3849.82 H7.9@2072.68,3872.32 ; U7.33@3180.36,3900.79 3388.82,3900.79 v1(3810,4321.97)
G57: H7.10 R128.2 U7.34 X2.13 | length 4322.5
  Top Layer w10: X2.13@1170,4039.96 1620.04,4039.96 1823.03,3836.97 H7.10@2108.03,3836.97 ; H7.10@2124.11,3844.11 2670,4390 3701.97,4390 v1(3810,4281.97)
  Bottom Layer w10: R128.2@1564.63,3816.87 2087.94,3816.87 H7.10@2108.03,3836.97 ; U7.34@3180.36,3881.1 3401.1,3881.1 v1@3805,4285
G58: H7.11 R130.2 U7.35 X2.14 | length 4352.9
  Top Layer w10: X2.14@1170,4020.28 1599.72,4020.28 1818.39,3801.61 H7.11@2143.39,3801.61 2701.78,4360 3695,4360 v1(3810,4245)
  Bottom Layer w10: R130.2@1594.63,3786.87 2128.65,3786.87 H7.11@2143.39,3801.61 ; U7.35@3180.36,3861.42 3424.26,3861.42 3807.84,4245 v1(3810,4245)
G59: H7.12 R132.2 U7.36 X2.15 | length 4361.3
  Top Layer w10: X2.15@1170,4000.59 1584.41,4000.59 1818.74,3766.26 H7.12@2178.74,3766.26 2742.49,4330 3690,4330 v1(3810,4210)
  Bottom Layer w10: R132.2@1622.58,3759.82 2172.31,3759.82 H7.12@2178.74,3766.26 ; U7.36@3180.36,3841.73 3441.73,3841.73 v1(3810,4210)
G60: H7.13 R134.2 U7.37 X2.16 | length 4448.5
  Top Layer w10: X2.16@1170,3980.91 1564.09,3980.91 1814.1,3730.9 H7.13@2214.1,3730.9 2788.2,4305 3665,4305 v1(3810,4160)
  Bottom Layer w10: R134.2@1650.53,3727.77 2210.97,3727.77 H7.13@2214.1,3730.9 ; U7.37@3123.27,3784.64 3431.46,3784.64 3806.82,4160 v1(3810,4160)
G61: H7.14 R136.2 U7.38 X2.17 | length 4554.5
  Top Layer w10: X2.17@1170,3961.22 1548.78,3961.22 1814.45,3695.55 2249.39,3695.55 H7.14@2249.45,3695.55 2249.45,3734.45 2795,4280 3651.82,4280 3806.82,4125 v1(3810,4125)
  Bottom Layer w10: R136.2@1680.53,3697.77 1687.61,3697.77 1689.83,3695.55 H7.14@2249.45,3695.55 ; U7.38@3103.58,3784.64 3103.58,3754.45 3106.76,3751.27 3106.76,3747.88 3116.43,3738.21 3423.21,3738.21 v1(3810,4125)
G62: H7.15 R139.2 U7.39 X2.18 | length 4629.9
  Top Layer w10: X2.18@1170,3941.54 1170.91,3940.63 1539.37,3940.63 1819.81,3660.19 H7.15@2284.81,3660.19 2284.81,3744.81 2795,4255 3640,4255 v1(3810,4085)
  Bottom Layer w10: R139.2@1712.58,3664.82 1719.65,3664.82 1724.29,3660.19 1737.36,3660.19 1741.33,3664.16 1750.45,3664.16 1754.42,3660.19 H7.15@2284.81,3660.19 ; U7.39@3083.9,3784.64 3083.9,3738.33 3100.23,3722 3443.21,3722 3806.21,4085 v1(3810,4085)
G63: H7.16 R141.2 U7.40 X2.19 | length 4691.4
  Top Layer w10: X2.19@1170,3921.85 1170.91,3920.94 1529.06,3920.94 1825.16,3624.84 H7.16@2320.16,3624.84 2320.16,3750.16 2800,4230 3625,4230 v1(3810,4045)
  Bottom Layer w10: R141.2@1745.53,3637.77 1752.61,3637.77 1765.54,3624.84 H7.16@2320.16,3624.84 ; U7.40@3064.21,3784.64 3064.21,3735.39 3093.6,3706 3471,3706 v1(3810,4045)
G64: H4.1 R143.2 U11.12 X2.20 | length 2393.2
  Top Layer w10: X2.20@1170,3902.17 1512.83,3902.17 1806.16,3608.84 2190.43,3608.84 H4.1@2312.13,3487.13
  Bottom Layer w10: R143.2@1819.07,3537.01 2166.08,3537.01 2215.96,3487.13 H4.1@2312.13,3487.13 2360,3535 2826.97,3535 2828.15,3533.82 2856.82,3533.82 U11.12@2857.1,3534.1
G65: H4.2 R145.2 U11.11 X2.21 | length 2405.6
  Top Layer w10: X2.21@1170,3882.48 1502.52,3882.48 1792.16,3592.84 2135.72,3592.84 H4.2@2276.78,3451.78
  Bottom Layer w10: R145.2@1789.07,3502.01 2178.46,3502.01 2228.69,3451.78 H4.2@2276.78,3451.78 ; H4.2@2272.89,3436.76 2280.43,3444.29 2318.35,3444.29 2354.97,3480.92 2354.97,3507.34 2362.63,3515 U11.11@2836.93,3515
G66: H4.3 R147.2 U11.10 X2.22 | length 2441.1
  Top Layer w10: X2.22@1170,3862.8 1487.2,3862.8 1773.16,3576.84 2081.01,3576.84 H4.3@2241.42,3416.42
  Bottom Layer w10: R147.2@1759.07,3467.01 2190.83,3467.01 H4.3@2241.42,3416.42 ; H4.3@2241.42,3415 2570,3415 2650,3495 U11.10@2889.77,3495
G67: H4.4 R149.2 U11.9 X2.23 | length 2438
  Top Layer w10: X2.23@1170,3843.11 1481.89,3843.11 1764.16,3560.84 2026.29,3560.84 H4.4@2206.07,3381.07
  Bottom Layer w10: R149.2@1729.07,3432.01 2155.12,3432.01 H4.4@2206.07,3381.07 ; H4.4@2201.1,3380 2570,3380 2665,3475 2827.47,3475 2827.7,3474.76 2873.79,3474.76 U11.9@2874.03,3475
G68: H4.5 R151.2 U11.8 X2.24 | length 2460.8
  Top Layer w10: X2.24@1170,3823.43 1466.57,3823.43 1745.16,3544.84 1971.59,3544.84 H4.5@2170.71,3345.71
  Bottom Layer w10: R151.2@1696.12,3399.96 2116.46,3399.96 H4.5@2170.71,3345.71 2570.83,3345.71 2680.12,3455 U11.8@2890.58,3455
G69: H4.6 R153.2 U11.7 X2.25 | length 2471
  Top Layer w10: X2.25@1170,3803.74 1451.26,3803.74 1726.16,3528.84 1916.87,3528.84 H4.6@2135.36,3310.36
  Bottom Layer w10: R153.2@1667.02,3369.06 2076.65,3369.06 H4.6@2135.36,3310.36 ; H4.6@2128.29,3310 2562.97,3310 2687.97,3435 2827.7,3435 U11.7@2885.18,3435
G70: H4.7 R155.2 U11.6 X2.26 | length 2461
  Top Layer w10: X2.26@1170,3784.06 1440.94,3784.06 1712.16,3512.84 1862.16,3512.84 H4.7@2100,3275
  Bottom Layer w10: R155.2@1637.02,3339.06 2035.94,3339.06 H4.7@2100,3275 ; H4.7@2106.82,3270 2550.8,3270 2695.8,3415 U11.6@2877.39,3415
G71: H4.8 R157.2 U11.5 X2.27 | length 2487.7
  Top Layer w10: X2.27@1170,3764.37 1428.26,3764.37 1695.79,3496.84 1807.45,3496.84 H4.8@2064.64,3239.64
  Bottom Layer w10: R157.2@1607.02,3304.06 2000.23,3304.06 H4.8@2064.29,3240 ; H4.8@2056.72,3240 H4.8@2064.29,3240 ; H4.8@2064.64,3239.64 H4.8@2064.29,3240 ; U11.5@2883.95,3395 2703.64,3395 2548.64,3240 H4.8@2064.29,3240
G72: H4.9 R159.2 U11.4 X2.28 | length 2484.9
  Top Layer w10: X2.28@1170,3744.69 1425.31,3744.69 1700,3470 1795,3470 2029.29,3235.71 H4.9@2029.29,3204.29
  Bottom Layer w10: R159.2@1577.02,3274.06 1959.52,3274.06 H4.9@2028.62,3204.96 ; H4.9@2027.3,3205 2027.34,3204.96 H4.9@2028.62,3204.96 ; H4.9@2029.29,3204.29 H4.9@2028.62,3204.96 ; U11.4@2858.54,3376.15 2712.62,3376.15 2541.48,3205 2079.05,3205 2079.01,3204.96 H4.9@2028.62,3204.96
G73: H4.10 R161.2 U11.3 X2.29 | length 2519
  Top Layer w10: X2.29@1170,3725 1405,3725 1685,3445 1780,3445 1993.93,3231.07 H4.10@1993.93,3168.93
  Bottom Layer w10: R161.2@1547.02,3244.06 1918.81,3244.06 H4.10@1993.26,3169.6 ; H4.10@1985.79,3170 1986.19,3169.6 H4.10@1993.26,3169.6 ; H4.10@1993.93,3168.93 H4.10@1993.26,3169.6 ; U11.3@2858.54,3356.46 2720.78,3356.46 2534.32,3170 2044.05,3170 2043.66,3169.6 H4.10@1993.26,3169.6
G74: H4.11 R163.2 U11.2 X2.30 | length 2537.4
  Top Layer w10: X2.30@1170,3705.32 1386.84,3705.32 1672.71,3419.45 1760.55,3419.45 1958.58,3221.42 H4.11@1958.58,3133.58
  Bottom Layer w10: R163.2@1517.02,3214.06 1878.1,3214.06 H4.11@1958.58,3133.58 ; H4.11@1958.58,3130 2522.15,3130 2728.93,3336.78 U11.2@2858.54,3336.78
G75: H4.12 R165.2 U11.1 X2.31 | length 2571.5
  Top Layer w10: X2.31@1170,3685.63 1369.37,3685.63 1663.07,3391.93 1743.07,3391.93 1923.22,3211.78 H4.12@1923.22,3098.22
  Bottom Layer w10: R165.2@1489.07,3182.01 1839.43,3182.01 H4.12@1921.45,3100 ; H4.12@1909.58,3100 H4.12@1921.45,3100 ; H4.12@1923.22,3098.22 H4.12@1921.45,3100 ; U11.1@2858.27,3317.28 2827.7,3317.28 2737.28,3317.28 2520,3100 1974.05,3100 1972.95,3098.89 1944.21,3098.89 1943.11,3100 H4.12@1921.45,3100
G76: H4.13 R167.2 U11.48 X2.32 | length 2628.7
  Top Layer w10: X2.32@1170,3665.95 1349.05,3665.95 1650.59,3364.41 1725.59,3364.41 1887.87,3202.13 H4.13@1887.87,3062.87
  Bottom Layer w10: R167.2@1459.07,3152.01 1798.72,3152.01 H4.13@1887.87,3062.87 ; H4.13@1885.67,3062.2 1887.87,3060 2510,3060 2710,3260 U11.48@2915.63,3260
G77: H4.14 R169.2 U11.47 X2.33 | length 2692.9
  Top Layer w10: X2.33@1170,3646.26 1323.74,3646.26 1633.11,3336.89 1703.11,3336.89 1852.51,3187.49 H4.14@1852.51,3027.51
  Bottom Layer w10: R169.2@1426.12,3119.96 1760.06,3119.96 H4.14@1852.51,3027.51 ; H4.14@1868.48,3025 2515,3025 2690.32,3200.32 2929.46,3200.32 2935.32,3206.18 U11.47@2935.32,3260
G78: H4.15 R171.2 U11.46 X2.34 | length 2768
  Top Layer w10: X2.34@1170,3626.58 1303.42,3626.58 1611.7,3318.3 1666.7,3318.3 1817.16,3167.84 H4.15@1817.16,2992.16
  Bottom Layer w10: R171.2@1394.07,3087.01 1722.3,3087.01 H4.15@1817.16,2992.16 ; H4.15@1817.16,2986.54 2511.54,2986.54 2696,3171 2937.16,3171 2955,3188.84 U11.46@2955,3260
G79: H4.16 R173.2 U11.45 X2.35 | length 2819.2
  Top Layer w10: X2.35@1170,3606.89 1288.11,3606.89 1600.23,3294.77 1635.23,3294.77 1781.8,3148.2 H4.16@1781.8,2956.8
  Bottom Layer w10: R173.2@1364.07,3057.01 1681.59,3057.01 H4.16@1781.8,2956.8 ; H4.16@1777.65,2955 2515,2955 2715,3155 2943.79,3155 2974.69,3185.9 U11.45@2974.69,3260
G80: H8.1 R175.2 U11.25 X2.36 | length 4785.9
  Top Layer w10: X2.36@1170,3587.21 1277.79,3587.21 1675,3190 1675,2885 1743.58,2816.42 H8.1@1778.58,2816.42 1897.16,2935 2900,2935 3746,3781 v1(3811.69,3781)
  Bottom Layer w10: R175.2@1284.69,2756.89 1719.05,2756.89 H8.1@1778.58,2816.42 ; U11.25@3189.26,3533.63 3219.45,3533.63 3224.45,3538.63 3488.63,3538.63 3735.03,3785.03 3770.26,3785.03 3774.29,3781 v1(3811.69,3781)
G81: H8.2 R177.2 U11.26 X2.37 | length 4823
  Top Layer w10: X2.37@1170,3567.52 1170.91,3566.61 1263.39,3566.61 1569.64,3260.36 1569.64,2919.64 1715.71,2773.58 1784.79,2773.58 1792.27,2781.07 H8.2@1813.93,2781.07 1947.87,2915 2944.75,2915 3779.75,3750 v1(3815.99,3750)
  Bottom Layer w10: R177.2@1317.64,2724.84 1757.71,2724.84 H8.2@1813.93,2781.07 ; U11.26@3189.26,3513.94 3508.94,3513.94 3745,3750 v1(3815.99,3750)
G82: H8.3 R179.2 U11.27 X2.38 | length 4842.1
  Top Layer w10: X2.38@1170,3547.84 1170.91,3546.93 1253.07,3546.93 1534.29,3265.71 1534.29,2884.29 1672.87,2745.71 H8.3@1849.29,2745.71 1993.58,2890 2942.37,2890 3767.37,3715 v1(3815,3715)
  Bottom Layer w10: R179.2@1347.64,2694.84 1798.42,2694.84 H8.3@1849.29,2745.71 ; U11.27@3189.26,3494.26 3539.26,3494.26 3760,3715 v1(3815,3715)
G83: H8.4 R181.2 U11.28 X2.39 | length 4869.4
  Top Layer w10: X2.39@1170,3528.15 1241.85,3528.15 1498.93,3271.07 1498.93,2848.93 1637.51,2710.35 H8.4@1884.65,2710.35 2039.29,2865 2940,2865 3755,3680 v1(3815,3680)
  Bottom Layer w10: R181.2@1377.64,2664.84 1839.13,2664.84 H8.4@1884.65,2710.35 ; U11.28@3189.26,3474.57 3549.57,3474.57 3755,3680 v1(3815,3680)
G84: H8.5 R183.2 U11.29 X2.40 | length 4893.7
  Top Layer w10: X2.40@1170,3508.47 1170.91,3507.56 1227.44,3507.56 1463.58,3271.42 1463.58,2813.58 1602.16,2675 H8.5@1920,2675 2090,2845 2950,2845 3750,3645 v1(3815,3645)
  Bottom Layer w10: R183.2@1407.64,2634.84 1879.84,2634.84 H8.5@1920,2675 ; U11.29@3189.26,3454.89 3569.89,3454.89 3760,3645 v1(3815,3645)
G85: H8.6 R185.2 U11.30 X2.41 | length 4923.8
  Top Layer w10: X2.41@1170,3488.78 1221.22,3488.78 1428.22,3281.78 1428.22,2778.22 1566.8,2639.64 H8.6@1955.36,2639.64 2135.71,2820 2970,2820 3755,3605 v1(3815.99,3605)
  Bottom Layer w10: R185.2@1437.64,2599.84 1915.55,2599.84 H8.6@1955.36,2639.64 ; U11.30@3189.26,3435.2 3580.2,3435.2 3750,3605 v1(3815.99,3605)
G86: H8.7 R187.2 U11.31 X2.42 | length 4945.8
  Top Layer w10: X2.42@1170,3469.1 1215.9,3469.1 1392.87,3292.13 1392.87,2742.87 1531.45,2604.29 1536.44,2604.29 ; 1536.44,2605 1940.95,2605 1940.99,2604.96 ; 1940.95,2604.29 H8.7@1990.71,2604.29 2176.42,2790 2975,2790 3745,3560 v1(3815.99,3560)
  Bottom Layer w10: R187.2@1467.64,2569.84 1956.26,2569.84 H8.7@1990.71,2604.29 ; U11.31@3189.26,3415.52 3615.52,3415.52 3760,3560 v1(3815.99,3560)
G87: H8.8 R189.2 U11.32 X2.43 | length 4969.1
  Top Layer w10: X2.43@1170,3449.41 1210.84,3449.41 1357.51,3302.74 1357.51,2707.51 1496.09,2568.93 H8.8@2026.07,2568.93 2212.13,2755 2965,2755 3730,3520 v1(3815.99,3520)
  Bottom Layer w10: R189.2@1499.69,2541.89 1999.02,2541.89 H8.8@2026.07,2568.93 ; U11.32@3189.26,3395.83 3640.83,3395.83 3765,3520 v1(3815.99,3520)
G88: H8.9 R191.2 U11.33 X2.44 | length 5009.1
  Top Layer w10: X2.44@1170,3429.73 1207.9,3429.73 1322.16,3315.47 1322.16,2672.16 1460.74,2533.58 H8.9@2061.42,2533.58 2252.84,2725 2970,2725 3730,3485 v1(3820,3485)
  Bottom Layer w10: R191.2@1532.64,2509.84 2037.68,2509.84 H8.9@2061.42,2533.58 ; U11.33@3189.26,3376.15 3666.15,3376.15 3720,3430 3720,3434.26 3770.74,3485 v1(3820,3485)
G89: H8.10 R193.2 U11.34 X2.45 | length 5039.7
  Top Layer w10: X2.45@1170,3410.04 1204.96,3410.04 1286.8,3328.2 1286.8,2636.8 1425.38,2498.22 1756.41,2498.22 ; 1756.41,2500 2045.95,2500 2047.05,2498.89 ; 2045.95,2498.22 H8.10@2096.78,2498.22 2293.55,2695 2990,2695 3745,3450 v1(3820,3450)
  Bottom Layer w10: R193.2@1562.64,2479.84 2078.39,2479.84 H8.10@2096.78,2498.22 ; U11.34@3189.26,3356.46 3681.46,3356.46 3775,3450 v1(3820,3450)
G90: H8.11 R195.2 U11.35 X3.1 | length 4281.9
  Top Layer w10: X3.1@1152.76,2433.07 1172.44,2433.07 1199.37,2460 2132.13,2460 H8.11@2135,2462.87 ; H8.11@2132.13,2462.87 2329.26,2660 2980,2660 3730,3410 v1(3820.99,3410)
  Bottom Layer w10: R195.2@1594.69,2446.89 2116.15,2446.89 H8.11@2132.13,2462.87 ; U11.35@3189.26,3336.78 3701.78,3336.78 3775,3410 v1(3820.99,3410)
G91: H8.12 R197.2 U11.36 X3.2 | length 4265.9
  Top Layer w10: X3.2@1152.7,2413.39 1153.6,2414.3 1656.66,2414.3 1670.55,2428.18 2166.82,2428.18 H8.12@2167.49,2427.51 2374.97,2635 3000,2635 3735,3370 v1(3820.99,3370)
  Bottom Layer w10: R197.2@1624.69,2416.89 2156.86,2416.89 H8.12@2167.49,2427.51 ; U11.36@3189.26,3317.09 3722.09,3317.09 3775,3370 v1(3820.99,3370)
G92: H8.13 R199.2 U11.37 X3.3 | length 4342.5
  Top Layer w10: X3.3@1152.76,2393.7 1153.63,2392.83 2200.67,2392.83 H8.13@2201.34,2392.16 ; H8.13@2202.84,2392.16 2425.69,2615 3030,2615 3750,3335 v1(3820,3335)
  Bottom Layer w10: R199.2@1654.69,2386.89 2197.57,2386.89 H8.13@2202.84,2392.16 ; U11.37@3132.17,3260 3132.17,3288 3132.64,3288.47 3738.47,3288.47 3785,3335 v1(3820,3335)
